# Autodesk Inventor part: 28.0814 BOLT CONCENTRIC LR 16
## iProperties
Created: 2009-01
Part Number: 28.0814 BOLT CONCENTRIC LR 16
Document SubType Name: Modeling
Designer: Administrator
Density: 7.85 g/cm^3
Material: Steel
Mass: 123.316 g
Surface Area: 47.2089 cm^2
Volume: 15.709 cm^3
Author: Administrator
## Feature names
1. Base1
